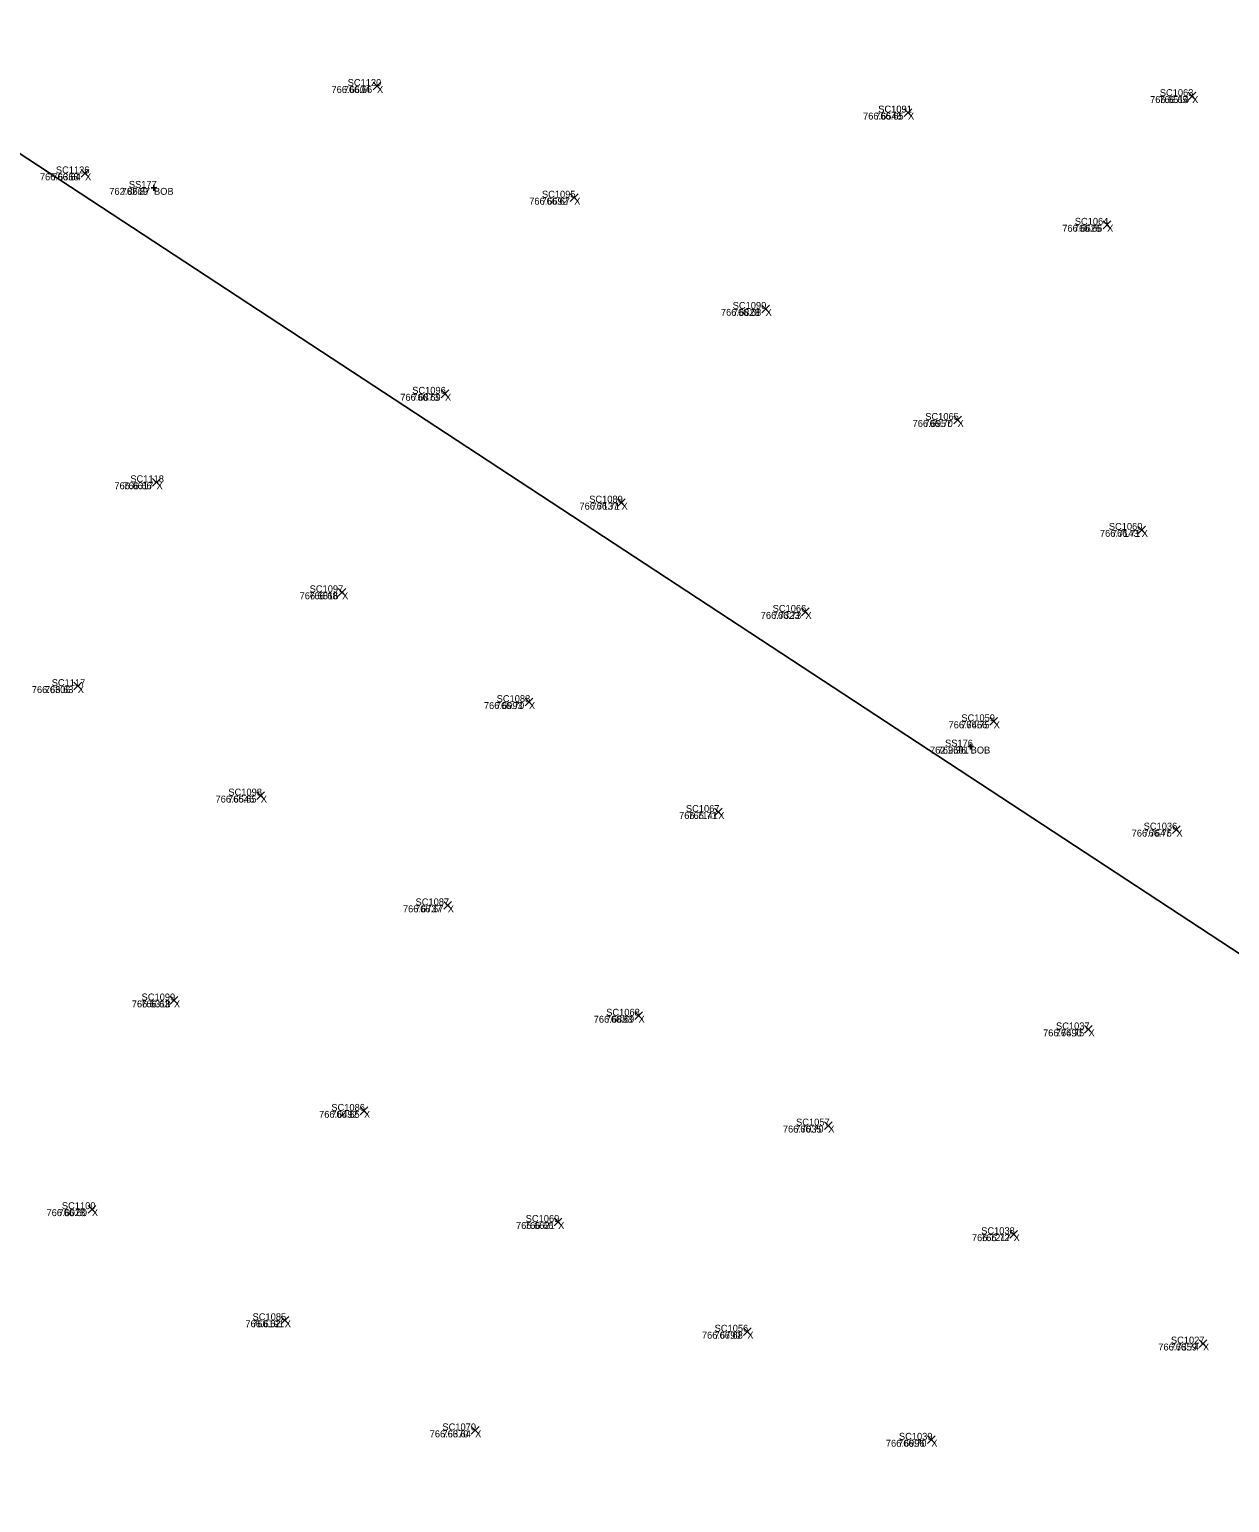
# Model space of a CAD drawing. Extents: x 1845019 to 1877956, y 680444 to 701081.
# Drawn here: x 1857571.05 to 1857581.41, y 694329.06 to 694341.78 of the extents above; entities that cross this region are included whole.
import ezdxf

# ---------------------------------------------------------------- set-up
doc = ezdxf.new("R2010")
doc.units = 0
for name, color, linetype in [('BR_X_SV_Bottom_of_Beam_Text', 7, 'Continuous'), ('SV_X_CL_Survey_20', 7, 'Continuous'), ('SV_X_Random_Point', 7, 'Continuous'), ('SV_X_Text_Comment', 7, 'Continuous'), ('SV_X_Text_Elevation', 7, 'Continuous'), ('SV_X_Text_Name', 7, 'Continuous')]:
    doc.layers.add(name, color=color, linetype=linetype)

msp = doc.modelspace()

# ---------------------------------------------------------------- linework, layer by layer
at = {"layer": 'BR_X_SV_Bottom_of_Beam_Text'}
for p, q in [((1857572.096, 694340.413), (1857572.146, 694340.413)), ((1857572.096, 694340.413), (1857572.146, 694340.413)), ((1857572.121, 694340.438), (1857572.121, 694340.388)), ((1857572.121, 694340.438), (1857572.121, 694340.388)), ((1857572.121, 694340.413), (1857572.121, 694340.413)), ((1857572.121, 694340.413), (1857572.121, 694340.413)), ((1857579.146, 694335.589), (1857579.196, 694335.589)), ((1857579.146, 694335.589), (1857579.196, 694335.589)), ((1857579.171, 694335.614), (1857579.171, 694335.564)), ((1857579.171, 694335.614), (1857579.171, 694335.564)), ((1857579.171, 694335.589), (1857579.171, 694335.589)), ((1857579.171, 694335.589), (1857579.171, 694335.589))]:
    msp.add_line(p, q, dxfattribs=at)
at = {"layer": 'SV_X_CL_Survey_20'}
msp.add_line((1856038.267, 695346.314), (1858797.327, 693536.085), dxfattribs=at)
at = {"layer": 'SV_X_Random_Point'}
for p, q in [((1857574.013, 694341.259), (1857574.08, 694341.326)), ((1857574.013, 694341.326), (1857574.08, 694341.259)), ((1857574.013, 694341.259), (1857574.08, 694341.326)), ((1857574.013, 694341.326), (1857574.08, 694341.259)), ((1857581.049, 694341.171), (1857581.116, 694341.238)), ((1857581.049, 694341.238), (1857581.116, 694341.171)), ((1857581.049, 694341.171), (1857581.116, 694341.238)), ((1857581.049, 694341.238), (1857581.116, 694341.171)), ((1857578.596, 694341.029), (1857578.663, 694341.096)), ((1857578.596, 694341.096), (1857578.663, 694341.029)), ((1857578.596, 694341.029), (1857578.663, 694341.096)), ((1857578.596, 694341.096), (1857578.663, 694341.029)), ((1857571.492, 694340.505), (1857571.559, 694340.572)), ((1857571.492, 694340.572), (1857571.559, 694340.505)), ((1857571.492, 694340.505), (1857571.559, 694340.572)), ((1857571.492, 694340.572), (1857571.559, 694340.505)), ((1857575.715, 694340.294), (1857575.782, 694340.361)), ((1857575.715, 694340.361), (1857575.782, 694340.294)), ((1857575.715, 694340.294), (1857575.782, 694340.361)), ((1857575.715, 694340.361), (1857575.782, 694340.294)), ((1857580.315, 694340.06), (1857580.382, 694340.127)), ((1857580.315, 694340.127), (1857580.382, 694340.06)), ((1857580.315, 694340.06), (1857580.382, 694340.127)), ((1857580.315, 694340.127), (1857580.382, 694340.06)), ((1857577.368, 694339.334), (1857577.435, 694339.401)), ((1857577.368, 694339.401), (1857577.435, 694339.334)), ((1857577.368, 694339.334), (1857577.435, 694339.401)), ((1857577.368, 694339.401), (1857577.435, 694339.334)), ((1857574.6, 694338.601), (1857574.667, 694338.668)), ((1857574.6, 694338.668), (1857574.667, 694338.601)), ((1857574.6, 694338.601), (1857574.667, 694338.668)), ((1857574.6, 694338.668), (1857574.667, 694338.601)), ((1857579.025, 694338.376), (1857579.091, 694338.442)), ((1857579.025, 694338.442), (1857579.091, 694338.376)), ((1857579.025, 694338.376), (1857579.091, 694338.442)), ((1857579.025, 694338.442), (1857579.091, 694338.376)), ((1857572.109, 694337.838), (1857572.176, 694337.904)), ((1857572.109, 694337.904), (1857572.176, 694337.838)), ((1857572.109, 694337.838), (1857572.176, 694337.904)), ((1857572.109, 694337.904), (1857572.176, 694337.838)), ((1857576.123, 694337.662), (1857576.19, 694337.728)), ((1857576.123, 694337.728), (1857576.19, 694337.662)), ((1857576.123, 694337.662), (1857576.19, 694337.728)), ((1857576.123, 694337.728), (1857576.19, 694337.662)), ((1857580.615, 694337.426), (1857580.682, 694337.493)), ((1857580.615, 694337.493), (1857580.682, 694337.426)), ((1857580.615, 694337.426), (1857580.682, 694337.493)), ((1857580.615, 694337.493), (1857580.682, 694337.426)), ((1857573.711, 694336.888), (1857573.778, 694336.955)), ((1857573.711, 694336.955), (1857573.778, 694336.888)), ((1857573.711, 694336.888), (1857573.778, 694336.955)), ((1857573.711, 694336.955), (1857573.778, 694336.888)), ((1857577.711, 694336.719), (1857577.778, 694336.786)), ((1857577.711, 694336.786), (1857577.778, 694336.719)), ((1857577.711, 694336.719), (1857577.778, 694336.786)), ((1857577.711, 694336.786), (1857577.778, 694336.719)), ((1857571.43, 694336.078), (1857571.497, 694336.144)), ((1857571.43, 694336.144), (1857571.497, 694336.078)), ((1857571.43, 694336.078), (1857571.497, 694336.144)), ((1857571.43, 694336.144), (1857571.497, 694336.078)), ((1857575.324, 694335.94), (1857575.391, 694336.007)), ((1857575.324, 694336.007), (1857575.391, 694335.94)), ((1857575.324, 694335.94), (1857575.391, 694336.007)), ((1857575.324, 694336.007), (1857575.391, 694335.94)), ((1857579.336, 694335.774), (1857579.403, 694335.841)), ((1857579.336, 694335.841), (1857579.403, 694335.774)), ((1857579.336, 694335.774), (1857579.403, 694335.841)), ((1857579.336, 694335.841), (1857579.403, 694335.774)), ((1857573.009, 694335.133), (1857573.076, 694335.199)), ((1857573.009, 694335.199), (1857573.076, 694335.133)), ((1857573.009, 694335.133), (1857573.076, 694335.199)), ((1857573.009, 694335.199), (1857573.076, 694335.133)), ((1857576.959, 694334.991), (1857577.026, 694335.058)), ((1857576.959, 694335.058), (1857577.026, 694334.991)), ((1857576.959, 694334.991), (1857577.026, 694335.058)), ((1857576.959, 694335.058), (1857577.026, 694334.991)), ((1857580.915, 694334.839), (1857580.981, 694334.905)), ((1857580.915, 694334.905), (1857580.981, 694334.839)), ((1857580.915, 694334.839), (1857580.981, 694334.905)), ((1857580.915, 694334.905), (1857580.981, 694334.839)), ((1857574.624, 694334.184), (1857574.69, 694334.251)), ((1857574.624, 694334.251), (1857574.69, 694334.184)), ((1857574.624, 694334.184), (1857574.69, 694334.251)), ((1857574.624, 694334.251), (1857574.69, 694334.184)), ((1857572.26, 694333.364), (1857572.327, 694333.431)), ((1857572.26, 694333.431), (1857572.327, 694333.364)), ((1857572.26, 694333.364), (1857572.327, 694333.431)), ((1857572.26, 694333.431), (1857572.327, 694333.364)), ((1857576.271, 694333.232), (1857576.338, 694333.299)), ((1857576.271, 694333.299), (1857576.338, 694333.232)), ((1857576.271, 694333.232), (1857576.338, 694333.299)), ((1857576.271, 694333.299), (1857576.338, 694333.232)), ((1857580.154, 694333.114), (1857580.221, 694333.18)), ((1857580.154, 694333.18), (1857580.221, 694333.114)), ((1857580.154, 694333.114), (1857580.221, 694333.18)), ((1857580.154, 694333.18), (1857580.221, 694333.114)), ((1857573.9, 694332.411), (1857573.967, 694332.478)), ((1857573.9, 694332.478), (1857573.967, 694332.411)), ((1857573.9, 694332.411), (1857573.967, 694332.478)), ((1857573.9, 694332.478), (1857573.967, 694332.411)), ((1857577.909, 694332.283), (1857577.975, 694332.35)), ((1857577.909, 694332.35), (1857577.975, 694332.283)), ((1857577.909, 694332.283), (1857577.975, 694332.35)), ((1857577.909, 694332.35), (1857577.975, 694332.283)), ((1857571.552, 694331.562), (1857571.619, 694331.628)), ((1857571.552, 694331.628), (1857571.619, 694331.562)), ((1857571.552, 694331.562), (1857571.619, 694331.628)), ((1857571.552, 694331.628), (1857571.619, 694331.562)), ((1857575.576, 694331.451), (1857575.643, 694331.517)), ((1857575.576, 694331.517), (1857575.643, 694331.451)), ((1857575.576, 694331.451), (1857575.643, 694331.517)), ((1857575.576, 694331.517), (1857575.643, 694331.451)), ((1857579.509, 694331.346), (1857579.575, 694331.412)), ((1857579.509, 694331.412), (1857579.575, 694331.346)), ((1857579.509, 694331.346), (1857579.575, 694331.412)), ((1857579.509, 694331.412), (1857579.575, 694331.346)), ((1857573.217, 694330.602), (1857573.284, 694330.669)), ((1857573.217, 694330.669), (1857573.284, 694330.602)), ((1857573.217, 694330.602), (1857573.284, 694330.669)), ((1857573.217, 694330.669), (1857573.284, 694330.602)), ((1857577.21, 694330.503), (1857577.276, 694330.57)), ((1857577.21, 694330.57), (1857577.276, 694330.503)), ((1857577.21, 694330.503), (1857577.276, 694330.57)), ((1857577.21, 694330.57), (1857577.276, 694330.503)), ((1857581.144, 694330.401), (1857581.211, 694330.468)), ((1857581.144, 694330.468), (1857581.211, 694330.401)), ((1857581.144, 694330.401), (1857581.211, 694330.468)), ((1857581.144, 694330.468), (1857581.211, 694330.401)), ((1857574.86, 694329.652), (1857574.927, 694329.718)), ((1857574.86, 694329.718), (1857574.927, 694329.652)), ((1857574.86, 694329.652), (1857574.927, 694329.718)), ((1857574.86, 694329.718), (1857574.927, 694329.652)), ((1857578.798, 694329.571), (1857578.865, 694329.637)), ((1857578.798, 694329.637), (1857578.865, 694329.571)), ((1857578.798, 694329.571), (1857578.865, 694329.637)), ((1857578.798, 694329.637), (1857578.865, 694329.571))]:
    msp.add_line(p, q, dxfattribs=at)

# ---------------------------------------------------------------- texts
at = {"layer": 'BR_X_SV_Bottom_of_Beam_Text'}
for s, p in [('762.8669', (1857571.735, 694340.353)), ('762.87', (1857571.841, 694340.353)), ('SS177', (1857571.904, 694340.413)), ('SS177', (1857571.904, 694340.413)), ('BOB', (1857572.121, 694340.353)), ('762.9601', (1857578.82, 694335.529)), ('762.96', (1857578.886, 694335.529)), ('SS176', (1857578.95, 694335.589)), ('SS176', (1857578.95, 694335.589)), ('BOB', (1857579.171, 694335.529))]:
    msp.add_text(s, height=0.06, dxfattribs=at).set_placement(p)
at = {"layer": 'SV_X_Text_Comment'}
for p in [(1857574.046, 694341.232), (1857581.083, 694341.145), (1857578.63, 694341.003), (1857571.526, 694340.478), (1857575.749, 694340.268), (1857580.349, 694340.034), (1857577.401, 694339.308), (1857574.633, 694338.575), (1857579.058, 694338.349), (1857572.143, 694337.811), (1857576.157, 694337.635), (1857580.648, 694337.4), (1857573.745, 694336.861), (1857577.745, 694336.692), (1857571.463, 694336.051), (1857575.358, 694335.913), (1857579.37, 694335.747), (1857573.043, 694335.106), (1857576.992, 694334.964), (1857580.948, 694334.812), (1857574.657, 694334.158), (1857572.293, 694333.337), (1857576.304, 694333.205), (1857580.188, 694333.087), (1857573.934, 694332.384), (1857577.942, 694332.257), (1857571.585, 694331.535), (1857575.61, 694331.424), (1857579.542, 694331.319), (1857573.25, 694330.576), (1857577.243, 694330.477), (1857581.177, 694330.375), (1857574.893, 694329.625), (1857578.831, 694329.544)]:
    msp.add_text('X', height=0.06, dxfattribs=at).set_placement(p)
at = {"layer": 'SV_X_Text_Elevation'}
for s, p in [('766.6604', (1857573.653, 694341.232)), ('766.66', (1857573.759, 694341.232)), ('766.6514', (1857580.72, 694341.145)), ('766.65', (1857580.8, 694341.145)), ('766.6548', (1857578.242, 694341.003)), ('766.65', (1857578.347, 694341.003)), ('766.6368', (1857571.136, 694340.478)), ('766.64', (1857571.243, 694340.478)), ('766.6692', (1857575.36, 694340.268)), ('766.67', (1857575.466, 694340.268)), ('766.6625', (1857579.962, 694340.034)), ('766.66', (1857580.062, 694340.034)), ('766.6828', (1857577.015, 694339.308)), ('766.68', (1857577.118, 694339.308)), ('766.6873', (1857574.247, 694338.575)), ('766.69', (1857574.35, 694338.575)), ('766.6957', (1857578.67, 694338.349)), ('766.70', (1857578.772, 694338.349)), ('766.6617', (1857571.779, 694337.811)), ('766.66', (1857571.856, 694337.811)), ('766.7137', (1857575.794, 694337.635)), ('766.71', (1857575.898, 694337.635)), ('766.7143', (1857580.287, 694337.4)), ('766.71', (1857580.39, 694337.4)), ('766.6816', (1857573.378, 694336.861)), ('766.68', (1857573.461, 694336.861)), ('766.7323', (1857577.359, 694336.692)), ('766.73', (1857577.463, 694336.692)), ('766.6306', (1857571.066, 694336.051)), ('766.63', (1857571.18, 694336.051)), ('766.6993', (1857574.969, 694335.913)), ('766.70', (1857575.072, 694335.913)), ('766.7466', (1857578.98, 694335.747)), ('766.75', (1857579.089, 694335.747)), ('766.6546', (1857572.652, 694335.106)), ('766.65', (1857572.76, 694335.106)), ('766.7141', (1857576.654, 694334.964)), ('766.71', (1857576.734, 694334.964)), ('766.7647', (1857580.561, 694334.812)), ('766.76', (1857580.663, 694334.812)), ('766.6737', (1857574.27, 694334.158)), ('766.67', (1857574.374, 694334.158)), ('766.6318', (1857571.929, 694333.337)), ('766.63', (1857572.01, 694333.337)), ('766.6883', (1857575.917, 694333.205)), ('766.69', (1857576.021, 694333.205)), ('766.7490', (1857579.796, 694333.087)), ('766.75', (1857579.906, 694333.087)), ('766.6492', (1857573.546, 694332.384)), ('766.65', (1857573.651, 694332.384)), ('766.7035', (1857577.55, 694332.257)), ('766.70', (1857577.656, 694332.257)), ('766.6028', (1857571.193, 694331.535)), ('766.60', (1857571.297, 694331.535)), ('766.6621', (1857575.246, 694331.424)), ('766.66', (1857575.323, 694331.424)), ('766.7217', (1857579.182, 694331.319)), ('766.72', (1857579.261, 694331.319)), ('766.6191', (1857572.91, 694330.576)), ('766.62', (1857572.968, 694330.576)), ('766.6790', (1857576.851, 694330.477)), ('766.68', (1857576.959, 694330.477)), ('766.7359', (1857580.791, 694330.375)), ('766.74', (1857580.897, 694330.375)), ('766.6370', (1857574.501, 694329.625)), ('766.64', (1857574.611, 694329.625)), ('766.6996', (1857578.439, 694329.544)), ('766.70', (1857578.545, 694329.544))]:
    msp.add_text(s, height=0.06, dxfattribs=at).set_placement(p)
at = {"layer": 'SV_X_Text_Name'}
for s, p in [('SC1120', (1857573.793, 694341.292)), ('SC1120', (1857573.793, 694341.292)), ('SC1063', (1857580.804, 694341.205)), ('SC1063', (1857580.804, 694341.205)), ('SC1091', (1857578.374, 694341.063)), ('SC1091', (1857578.373, 694341.063)), ('SC1126', (1857571.274, 694340.538)), ('SC1126', (1857571.274, 694340.538)), ('SC1095', (1857575.47, 694340.328)), ('SC1095', (1857575.47, 694340.328)), ('SC1064', (1857580.07, 694340.094)), ('SC1064', (1857580.07, 694340.094)), ('SC1090', (1857577.117, 694339.368)), ('SC1090', (1857577.117, 694339.368)), ('SC1096', (1857574.35, 694338.635)), ('SC1096', (1857574.35, 694338.635)), ('SC1065', (1857578.779, 694338.409)), ('SC1065', (1857578.779, 694338.409)), ('SC1118', (1857571.917, 694337.871)), ('SC1118', (1857571.917, 694337.871)), ('SC1089', (1857575.878, 694337.695)), ('SC1089', (1857575.878, 694337.695)), ('SC1060', (1857580.364, 694337.46)), ('SC1060', (1857580.364, 694337.46)), ('SC1097', (1857573.465, 694336.921)), ('SC1097', (1857573.465, 694336.921)), ('SC1066', (1857577.462, 694336.752)), ('SC1066', (1857577.462, 694336.752)), ('SC1117', (1857571.238, 694336.111)), ('SC1117', (1857571.238, 694336.111)), ('SC1088', (1857575.079, 694335.973)), ('SC1088', (1857575.079, 694335.973)), ('SC1059', (1857579.091, 694335.807)), ('SC1059', (1857579.091, 694335.807)), ('SC1098', (1857572.763, 694335.166)), ('SC1098', (1857572.763, 694335.166)), ('SC1067', (1857576.713, 694335.024)), ('SC1067', (1857576.713, 694335.024)), ('SC1036', (1857580.665, 694334.872)), ('SC1036', (1857580.665, 694334.872)), ('SC1087', (1857574.379, 694334.218)), ('SC1087', (1857574.379, 694334.218)), ('SC1099', (1857572.014, 694333.397)), ('SC1099', (1857572.014, 694333.397)), ('SC1068', (1857576.025, 694333.265)), ('SC1068', (1857576.025, 694333.265)), ('SC1037', (1857579.908, 694333.147)), ('SC1037', (1857579.908, 694333.147)), ('SC1086', (1857573.652, 694332.444)), ('SC1086', (1857573.652, 694332.444)), ('SC1057', (1857577.664, 694332.317)), ('SC1057', (1857577.664, 694332.317)), ('SC1100', (1857571.326, 694331.595)), ('SC1100', (1857571.326, 694331.595)), ('SC1069', (1857575.33, 694331.484)), ('SC1069', (1857575.33, 694331.484)), ('SC1038', (1857579.262, 694331.379)), ('SC1038', (1857579.262, 694331.379)), ('SC1085', (1857572.972, 694330.636)), ('SC1085', (1857572.972, 694330.636)), ('SC1056', (1857576.961, 694330.537)), ('SC1056', (1857576.961, 694330.537)), ('SC1027', (1857580.9, 694330.435)), ('SC1027', (1857580.9, 694330.435)), ('SC1070', (1857574.611, 694329.685)), ('SC1070', (1857574.611, 694329.685)), ('SC1039', (1857578.552, 694329.604)), ('SC1039', (1857578.552, 694329.604))]:
    msp.add_text(s, height=0.06, dxfattribs=at).set_placement(p)

doc.saveas('drawing.dxf')
